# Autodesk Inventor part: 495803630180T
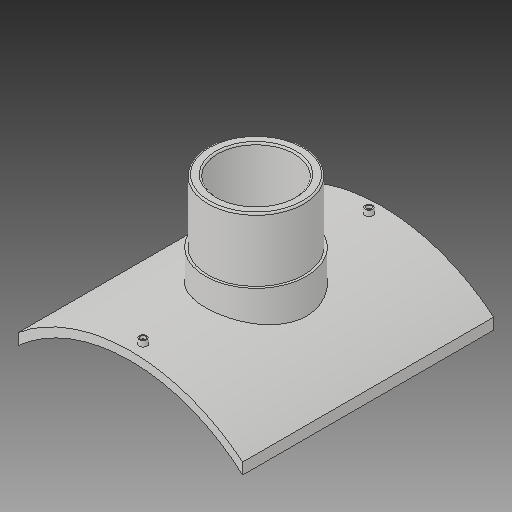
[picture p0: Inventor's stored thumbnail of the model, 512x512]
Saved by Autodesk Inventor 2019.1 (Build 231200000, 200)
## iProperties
Created: 2017-10
Part Number: 495803630180T
Material: Generic
Description: PLASSON BRANCH SADDLE  630x180
Document SubType Name: Modeling
Designer: KIM
Mass: 2754.05 g
Surface Area: 3037.44 cm^2
Volume: 2754.05 cm^3
Density: 1 g/cm^3
Appearance: Default
Author: KIM
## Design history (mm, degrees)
derived "495803.ipt"
feature "Solid1::495803.ipt"
tag "TaggingFeature1"
body "Solid1"
other parameters: "d1" = 16, "d4" = 0, "d12" = 340.6, "d13" = 14, "d14" = 211.5, "d16" = 5 deg, "d18" = 4, "d19" = 14, "d20" = 0, "d21" = 3, "d22" = 0, "d24" = 189, "d25" = 16, "d26" = 144, "d28" = 0, "d29" = 9.6, "d31" = 0, "d32" = 84.5, "d33" = 0, "d34" = 6.3, "d37" = 118.3, "d38" = 0, "d39" = 3.15, "H_" = 169, "x_" = 16, "D_" = 16
